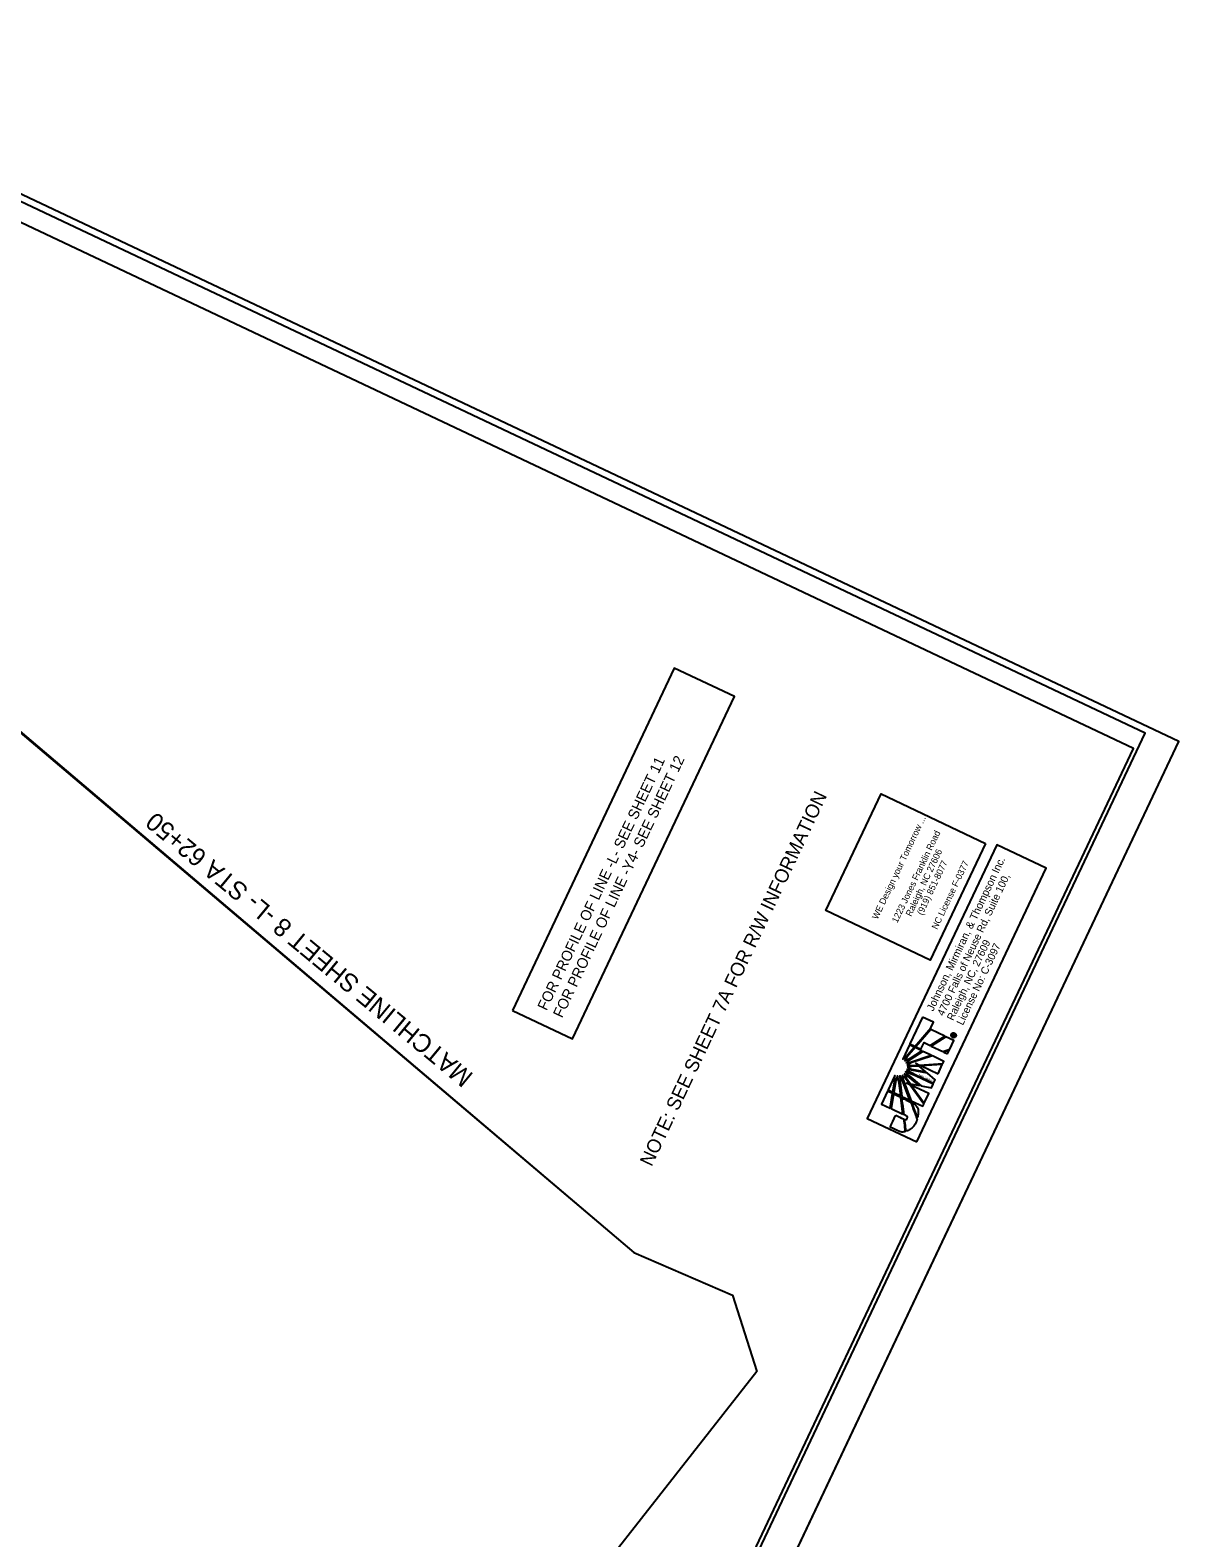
# Model space of a CAD drawing. Extents: x 556536 to 558250, y 505355 to 507347.
# Drawn here: x 557491 to 558250, y 506351 to 507347 of the extents above; entities that cross this region are included whole.
import ezdxf

# ---------------------------------------------------------------- set-up
doc = ezdxf.new("R2010")
doc.units = 0
for name, color, linetype in [('Prop Drainage Structure Box Number Symbol CELL', 7, 'Continuous'), ('Prop Drainage Structure Catch Basin Grate 840 03G CELL', 7, 'Continuous'), ('Prop Drainage Structure Pipe Alternate 15in Label', 7, 'Continuous'), ('Prop Drainage Structure Pipe Alternate 36in', 7, 'Continuous'), ('Prop Earthen Structure Base Ditch Lateral Detail Label', 7, 'Continuous'), ('Prop Earthen Structure Berm Ditch Detail CELL', 7, 'Continuous'), ('Prop Earthen Structure Berm Ditch Detail Label', 7, 'Continuous'), ('Prop Earthen Structure V Ditch Lateral Detail CELL', 7, 'Continuous'), ('Prop Erosion Rip Rap Class B', 7, 'Continuous')]:
    doc.layers.add(name, color=color, linetype=linetype)

msp = doc.modelspace()

# ---------------------------------------------------------------- linework, layer by layer
at = {"layer": 'Prop Drainage Structure Box Number Symbol CELL'}
msp.add_lwpolyline([(557273.74, 507333.49), (556561.61, 505826.81), (557515.52, 505375.94), (558227.66, 506882.62)], close=True, dxfattribs=at)
at = {"layer": 'Prop Drainage Structure Catch Basin Grate 840 03G CELL'}
msp.add_lwpolyline([(557798.52, 506240.88), (557748.79, 506156.98), (557718.06, 506089.72), (557705.43, 506089.79), (557646.19, 505968.9), (557731.53, 505869.1), (557643.42, 505687.13), (557512.37, 505750.31), (557008.7, 505860.07), (556630.15, 505965.86), (557185.22, 507140.23), (557323.61, 507073.55), (557372.9, 507178.95), (557443.19, 507138.35), (557473.73, 506971.77), (557393.31, 506960), (557425.46, 506933.59), (557889.73, 506539.36), (557955.03, 506511.13), (557971.08, 506460.75)], close=True, dxfattribs=at)
at = {"layer": 'Prop Drainage Structure Pipe Alternate 15in Label'}
msp.add_lwpolyline([(558122.18, 506809.73), (558085.58, 506732.64), (558016.57, 506765.41), (558053.17, 506842.5)], close=True, dxfattribs=at)
at = {"layer": 'Prop Drainage Structure Pipe Alternate 36in'}
msp.add_lwpolyline([(557809.53, 506699.41), (557849.33, 506680.6), (557956.24, 506906.79), (557916.44, 506925.6), (557809.53, 506699.41)], dxfattribs=at)
at = {"layer": 'Prop Earthen Structure Base Ditch Lateral Detail Label'}
msp.add_lwpolyline([(557255.37, 507347.15), (556535.75, 505824.65), (557530.26, 505354.59), (558249.88, 506877.09)], close=True, dxfattribs=at)
at = {"layer": 'Prop Earthen Structure Berm Ditch Detail Label'}
msp.add_line((557530.26, 505354.59), (558249.88, 506877.09), dxfattribs=at)
at = {"layer": 'Prop Earthen Structure V Ditch Lateral Detail CELL'}
for p, q in [((557393.31, 506960), (557889.73, 506539.36)), ((558080.53, 506695.03), (558072.14, 506677.23)), ((558075.51, 506675.65), (558086.04, 506687.81)), ((558087.82, 506691.6), (558080.53, 506695.03)), ((558086.04, 506687.81), (558087.82, 506691.6)), ((558085.94, 506686.76), (558076.01, 506675.41)), ((558079.47, 506673.78), (558081.52, 506678.12)), ((558081.52, 506678.12), (558085.59, 506676.2)), ((558085.59, 506676.2), (558095.29, 506682.36)), ((558095.29, 506682.36), (558085.94, 506686.76)), ((558095.94, 506682.05), (558086.29, 506675.87)), ((558101.2, 506679.57), (558095.94, 506682.05)), ((558098.49, 506673.83), (558101.2, 506679.57)), ((558099.64, 506683.68), (558099.91, 506683.55)), ((558099.91, 506683.55), (558099.64, 506683.68)), ((558100.15, 506682.79), (558100.4, 506683.32)), ((558101.45, 506682.18), (558100.15, 506682.79)), ((558100.4, 506683.32), (558100.44, 506683.4)), ((558100.4, 506683.32), (558100.65, 506683.2)), ((558100.65, 506683.2), (558100.4, 506683.32)), ((558100.65, 506683.2), (558100.54, 506682.96)), ((558100.54, 506682.96), (558100.85, 506682.82)), ((558100.67, 506683.23), (558100.65, 506683.2)), ((558100.85, 506682.82), (558100.96, 506683.05)), ((558100.96, 506683.05), (558100.96, 506683.07)), ((558100.96, 506683.05), (558101.19, 506682.94)), ((558101.19, 506682.94), (558100.96, 506683.05)), ((558101.19, 506682.94), (558101.08, 506682.71)), ((558101.08, 506682.71), (558101.59, 506682.47)), ((558101.2, 506682.96), (558101.19, 506682.94)), ((558101.59, 506682.47), (558101.45, 506682.18)), ((558102.2, 506682.47), (558102.21, 506682.48)), ((558102.2, 506682.47), (558102.49, 506682.33)), ((558102.49, 506682.33), (558102.2, 506682.47)), ((558102.49, 506682.35), (558102.49, 506682.33)), ((558071.87, 506676.56), (558067.4, 506667.19)), ((558067.4, 506667.19), (558069.64, 506669.04)), ((558070.14, 506668.51), (558068.57, 506666.05)), ((558068.57, 506666.05), (558073.15, 506668.23)), ((558069.64, 506669.04), (558074.92, 506675.12)), ((558075.56, 506674.82), (558070.14, 506668.51)), ((558074.92, 506675.12), (558071.87, 506676.56)), ((558072.14, 506677.23), (558075.41, 506675.69)), ((558072.64, 506665.23), (558086.19, 506669.74)), ((558080.77, 506672.29), (558072.71, 506667.19)), ((558087.07, 506669.32), (558072.88, 506664.65)), ((558073.15, 506668.23), (558080.02, 506672.65)), ((558075.41, 506675.69), (558075.51, 506675.65)), ((558080.02, 506672.65), (558075.56, 506674.82)), ((558076.01, 506675.41), (558076.06, 506675.38)), ((558076.06, 506675.38), (558079.47, 506673.78)), ((558086.19, 506669.74), (558080.77, 506672.29)), ((558086.29, 506675.87), (558093.86, 506672.3)), ((558094.67, 506665.74), (558087.07, 506669.32)), ((558093.86, 506672.3), (558098.49, 506673.83)), ((558098.09, 506672.99), (558094.68, 506671.91)), ((558094.68, 506671.91), (558097.06, 506670.8)), ((558097.06, 506670.8), (558098.09, 506672.99)), ((558076.21, 506655.95), (558069.36, 506658.73)), ((558069.36, 506658.73), (558071.52, 506656.3)), ((558072.71, 506667.19), (558069.54, 506664.69)), ((558069.54, 506664.69), (558072.64, 506665.23)), ((558070.02, 506660.13), (558076.49, 506656.55)), ((558073.25, 506659.97), (558070.02, 506660.13)), ((558072.88, 506664.65), (558070.09, 506663.22)), ((558070.09, 506663.22), (558073.29, 506662.98)), ((558073.2, 506662.28), (558070.28, 506661.66)), ((558070.28, 506661.66), (558073.12, 506660.67)), ((558073.12, 506660.67), (558082.71, 506658.83)), ((558078.2, 506662.61), (558073.2, 506662.28)), ((558083.69, 506658.02), (558073.25, 506659.97)), ((558073.29, 506662.98), (558077.51, 506663.21)), ((558077.51, 506663.21), (558076.04, 506664.43)), ((558076.04, 506664.43), (558078.51, 506663.26)), ((558082.71, 506658.83), (558078.2, 506662.61)), ((558078.51, 506663.26), (558093.97, 506664.24)), ((558093.6, 506663.56), (558079.73, 506662.69)), ((558079.73, 506662.69), (558090.74, 506657.5)), ((558088.89, 506653.57), (558083.69, 506658.02)), ((558090.74, 506657.5), (558093.6, 506663.56)), ((558093.97, 506664.24), (558094.67, 506665.74)), ((558062.32, 506656.4), (558057.82, 506646.87)), ((558060.85, 506645.44), (558062.24, 506653.46)), ((558062.9, 506653.15), (558061.51, 506645.13)), ((558062.24, 506653.46), (558062.32, 506656.4)), ((558063.87, 506656.08), (558062.9, 506653.15)), ((558065.07, 506651.23), (558063.87, 506656.08)), ((558066.09, 506642.97), (558065.07, 506651.23)), ((558067.03, 506653.44), (558065.51, 506656.16)), ((558065.51, 506656.16), (558065.63, 506652.16)), ((558065.63, 506652.16), (558066.83, 506642.62)), ((558066.99, 506656.65), (558067.67, 506653.59)), ((558069.22, 506654.34), (558066.99, 506656.65)), ((558072.12, 506640.13), (558067.03, 506653.44)), ((558067.67, 506653.59), (558073.01, 506639.71)), ((558068.32, 506657.51), (558069.68, 506654.82)), ((558070.82, 506656.04), (558068.32, 506657.51)), ((558071.61, 506651.05), (558069.22, 506654.34)), ((558069.68, 506654.82), (558072.52, 506650.91)), ((558072.11, 506650.3), (558069.87, 506651.35)), ((558069.87, 506651.35), (558071.61, 506651.05)), ((558078.24, 506649.87), (558070.82, 506656.04)), ((558071.52, 506656.3), (558079.55, 506649.59)), ((558081.35, 506637.48), (558072.11, 506650.3)), ((558072.52, 506650.91), (558078.24, 506649.87)), ((558084.64, 506644.46), (558073.33, 506649.72)), ((558073.33, 506649.72), (558081.66, 506638.14)), ((558087.5, 506650.62), (558076.21, 506655.95)), ((558076.49, 506656.55), (558087.78, 506651.23)), ((558079.55, 506649.59), (558086.4, 506648.31)), ((558086.4, 506648.31), (558087.5, 506650.62)), ((558087.78, 506651.23), (558088.89, 506653.57)), ((558057.45, 506645.97), (558053.46, 506637.5)), ((558060.72, 506644.43), (558057.45, 506645.97)), ((558057.82, 506646.87), (558060.85, 506645.44)), ((558059.07, 506634.86), (558060.72, 506644.43)), ((558061.33, 506644.14), (558059.72, 506634.55)), ((558066.24, 506641.83), (558061.33, 506644.14)), ((558061.51, 506645.13), (558066.09, 506642.97)), ((558067.61, 506630.83), (558066.24, 506641.83)), ((558066.83, 506642.62), (558072.12, 506640.13)), ((558073.01, 506639.71), (558080.7, 506636.09)), ((558081.66, 506638.14), (558084.64, 506644.46)), ((558053.46, 506637.5), (558059.07, 506634.86)), ((558059.72, 506634.55), (558067.61, 506630.83)), ((558080.7, 506636.09), (558081.35, 506637.48))]:
    msp.add_line(p, q, dxfattribs=at)
msp.add_lwpolyline([(558076.68, 506612.53), (558162.16, 506793.38), (558129.52, 506808.8), (558044.04, 506627.95)], close=True, dxfattribs=at)
for points in [[(558080.53, 506695.03), (558072.14, 506677.23), (558075.41, 506675.69), (558075.51, 506675.65), (558086.04, 506687.81), (558087.82, 506691.6), (558080.53, 506695.03)], [(558076.01, 506675.41), (558076.06, 506675.38), (558079.47, 506673.78), (558081.52, 506678.12), (558085.59, 506676.2), (558095.29, 506682.36), (558085.94, 506686.76), (558076.01, 506675.41)], [(558086.29, 506675.87), (558093.86, 506672.3), (558098.49, 506673.83), (558101.2, 506679.57), (558095.94, 506682.05), (558086.29, 506675.87), (558086.29, 506675.87)], [(558101.66, 506683.41), (558101.73, 506683.38), (558101.78, 506683.37), (558101.83, 506683.35), (558101.99, 506683.32), (558101.86, 506683.05)], [(558069.64, 506669.04), (558074.92, 506675.12), (558071.87, 506676.56), (558067.4, 506667.19), (558069.64, 506669.04)], [(558068.57, 506666.05), (558073.15, 506668.23), (558080.02, 506672.65), (558075.56, 506674.82), (558070.14, 506668.51), (558068.57, 506666.05)], [(558069.54, 506664.69), (558072.64, 506665.23), (558086.19, 506669.74), (558080.77, 506672.29), (558072.71, 506667.19), (558069.54, 506664.69)], [(558070.09, 506663.22), (558073.29, 506662.98), (558077.51, 506663.21), (558076.04, 506664.43), (558078.51, 506663.26), (558093.97, 506664.24), (558094.67, 506665.74), (558087.07, 506669.32), (558072.88, 506664.65), (558070.09, 506663.22)], [(558097.06, 506670.8), (558097.06, 506670.8), (558098.09, 506672.99), (558094.68, 506671.91), (558097.06, 506670.8)], [(558071.52, 506656.3), (558079.55, 506649.59), (558086.4, 506648.31), (558087.5, 506650.62), (558076.21, 506655.95), (558069.36, 506658.73), (558071.52, 506656.3)], [(558070.02, 506660.13), (558076.49, 506656.55), (558087.78, 506651.23), (558088.89, 506653.57), (558083.69, 506658.02), (558073.25, 506659.97), (558070.02, 506660.13)], [(558070.28, 506661.66), (558073.12, 506660.67), (558082.71, 506658.83), (558078.2, 506662.61), (558073.2, 506662.28), (558070.28, 506661.66)], [(558090.74, 506657.5), (558093.6, 506663.56), (558079.73, 506662.69), (558090.74, 506657.5)], [(558062.24, 506653.46), (558062.32, 506656.4), (558057.82, 506646.87), (558060.85, 506645.44), (558062.24, 506653.46)], [(558061.51, 506645.13), (558066.09, 506642.97), (558065.07, 506651.23), (558063.87, 506656.08), (558062.9, 506653.15), (558061.51, 506645.13)], [(558066.83, 506642.62), (558072.12, 506640.13), (558067.03, 506653.44), (558065.51, 506656.16), (558065.63, 506652.16), (558066.83, 506642.62)], [(558066.99, 506656.65), (558067.67, 506653.59), (558073.01, 506639.71), (558080.7, 506636.09), (558081.35, 506637.48), (558072.11, 506650.3), (558069.87, 506651.35), (558071.61, 506651.05), (558069.22, 506654.34), (558066.99, 506656.65)], [(558068.32, 506657.51), (558069.68, 506654.82), (558072.52, 506650.91), (558078.24, 506649.87), (558070.82, 506656.04), (558068.32, 506657.51)], [(558081.66, 506638.14), (558084.64, 506644.46), (558073.33, 506649.72), (558081.66, 506638.14)], [(558059.07, 506634.86), (558060.72, 506644.43), (558057.45, 506645.97), (558053.46, 506637.5), (558059.07, 506634.86)], [(558067.61, 506630.83), (558066.24, 506641.83), (558061.33, 506644.14), (558059.72, 506634.55), (558067.61, 506630.83)]]:
    msp.add_lwpolyline(points, dxfattribs=at)
for points, degree in [([(558102.49, 506682.33), (558102.3, 506681.95), (558102, 506681.67), (558101.59, 506681.52), (558101.18, 506681.37), (558100.77, 506681.39), (558100.37, 506681.58), (558099.97, 506681.76), (558099.7, 506682.07), (558099.57, 506682.47), (558099.44, 506682.88), (558099.45, 506683.28), (558099.64, 506683.68)], 3), ([(558099.64, 506683.68), (558099.83, 506684.08), (558100.13, 506684.35), (558100.53, 506684.51), (558100.93, 506684.67), (558101.33, 506684.65), (558101.73, 506684.46)], 3), ([(558099.91, 506683.55), (558099.76, 506683.23), (558099.74, 506682.91), (558099.84, 506682.59), (558099.96, 506682.26), (558100.19, 506682.01), (558100.51, 506681.86), (558100.82, 506681.71), (558101.16, 506681.69), (558101.49, 506681.81), (558101.82, 506681.93), (558102.05, 506682.15), (558102.2, 506682.47)], 3), ([(558102.21, 506682.48), (558102.36, 506682.8), (558102.38, 506683.12), (558102.26, 506683.45), (558102.14, 506683.78), (558101.92, 506684.03), (558101.6, 506684.18), (558101.28, 506684.33), (558100.94, 506684.34), (558100.62, 506684.22), (558100.3, 506684.1), (558100.06, 506683.88), (558099.91, 506683.55)], 3), ([(558100.44, 506683.4), (558100.6, 506683.73), (558100.81, 506683.83), (558101.06, 506683.71), (558101.18, 506683.65), (558101.25, 506683.56), (558101.27, 506683.42)], 3), ([(558100.96, 506683.07), (558101.05, 506683.26), (558101.04, 506683.38), (558100.93, 506683.43), (558100.84, 506683.47), (558100.75, 506683.41), (558100.67, 506683.23)], 3), ([(558101.35, 506683.16), (558101.31, 506683.13), (558101.25, 506683.07), (558101.2, 506682.96)], 2), ([(558101.27, 506683.42), (558101.36, 506683.48), (558101.49, 506683.48), (558101.66, 506683.41)], 2), ([(558101.86, 506683.05), (558101.77, 506683.05), (558101.69, 506683.05), (558101.6, 506683.1), (558101.48, 506683.15), (558101.4, 506683.18), (558101.35, 506683.16)], 3), ([(558101.73, 506684.46), (558102.13, 506684.27), (558102.41, 506683.97), (558102.56, 506683.56), (558102.7, 506683.15), (558102.68, 506682.75), (558102.49, 506682.35)], 3), ([(558070.46, 506628), (558070.22, 506627.5), (558069.74, 506627.2), (558068.72, 506627.46), (558068.72, 506627.46), (558069.61, 506619.61), (558069.61, 506619.61), (558072.46, 506620.55), (558075.05, 506622.99), (558076.24, 506625.52), (558076.55, 506626.17), (558076.73, 506626.7), (558076.92, 506627.47), (558076.92, 506627.47), (558072.64, 506638.81), (558072.64, 506638.81), (558072.64, 506638.81), (558066.94, 506641.5), (558066.94, 506641.5), (558066.94, 506641.5), (558068.32, 506630.5), (558068.32, 506630.5), (558070.46, 506629.49), (558070.79, 506628.7), (558070.46, 506628)], 3), ([(558070.46, 506628), (558070.22, 506627.5), (558069.74, 506627.2), (558068.72, 506627.46), (558068.72, 506627.46), (558069.61, 506619.61), (558069.61, 506619.61), (558072.46, 506620.55), (558075.05, 506622.99), (558076.24, 506625.52), (558076.55, 506626.17), (558076.73, 506626.7), (558076.92, 506627.47), (558076.92, 506627.47), (558072.64, 506638.81), (558072.64, 506638.81), (558072.64, 506638.81), (558066.94, 506641.5), (558066.94, 506641.5), (558066.94, 506641.5), (558068.32, 506630.5), (558068.32, 506630.5), (558070.46, 506629.49), (558070.79, 506628.7), (558070.46, 506628)], 3), ([(558073.53, 506638.39), (558073.53, 506638.39), (558077.23, 506628.59), (558077.23, 506628.59), (558077.95, 506632.19), (558077.33, 506636.41), (558073.53, 506638.39)], 3), ([(558062.83, 506630.11), (558062.83, 506630.11), (558059.14, 506622.27), (558059.14, 506622.27), (558059.14, 506622.27), (558064.04, 506619.96), (558064.04, 506619.96), (558064.04, 506619.96), (558064.56, 506619.72), (558064.56, 506619.72), (558066.09, 506618.99), (558067.55, 506618.92), (558068.99, 506619.34), (558068.99, 506619.34), (558068.11, 506627.62), (558068.02, 506627.67), (558068.02, 506627.67), (558062.83, 506630.11), (558062.83, 506630.11)], 3)]:
    msp.add_open_spline(points, degree=degree, dxfattribs=at)
at = {"layer": 'Prop Erosion Rip Rap Class B'}
msp.add_lwpolyline([(557270.71, 507321.1), (556629.72, 505964.95), (557579.02, 505516.26), (558220.01, 506872.41)], close=True, dxfattribs=at)

# ---------------------------------------------------------------- texts
at = {"layer": 'Prop Drainage Structure Pipe Alternate 15in Label'}
for s, p in [('WE Design your Tomorrow ...', (558050.8, 506759.16)), ('1223 Jones Franklin Road', (558063.86, 506756.83)), ('Raleigh, NC 27606', (558072.99, 506761.14)), ('(919) 851-8077', (558080.46, 506761.96)), ('NC License F-0377', (558090.16, 506752.54))]:
    msp.add_text(s, height=4.2667, rotation=64.59913, dxfattribs=at).set_placement(p)
at = {"layer": 'Prop Drainage Structure Pipe Alternate 36in'}
for s, height, p in [('FOR PROFILE OF LINE -Y4- SEE SHEET 12', 7, (557842.35, 506693.96)), ('FOR PROFILE OF LINE -L- SEE SHEET 11', 7, (557832.07, 506698.82)), ('NOTE: SEE SHEET 7A FOR R/W INFORMATION', 9.1, (557901.52, 506595.72))]:
    msp.add_text(s, height=height, rotation=64.7021, dxfattribs=at).set_placement(p)
at = {"layer": 'Prop Earthen Structure Berm Ditch Detail CELL'}
msp.add_text('MATCHLINE SHEET 8 -L- STA 62+50', height=12, rotation=140.41535, dxfattribs=at).set_placement((557784.37, 506657.04))
at = {"layer": 'Prop Earthen Structure V Ditch Lateral Detail CELL'}
for s, height, rotation, p in [('Johnson, Mirmiran, & Thompson Inc.', 5.1112, 64.7021, (558087.6, 506698.48)), ('4700 Falls of Neuse Rd, Suite 100, ', 4.9652, 64.7021, (558094.38, 506695.27)), ('Raleigh, NC, 27609', 4.9652, 64.7021, (558100.8, 506692.24)), ('License No: C-3097', 4.9652, 64.7021, (558107.21, 506689.21)), ('www.jmt.com', 1.2413, 334.7021, (558077.91, 506656.57))]:
    msp.add_text(s, height=height, rotation=rotation, dxfattribs=at).set_placement(p)

doc.saveas('drawing.dxf')
